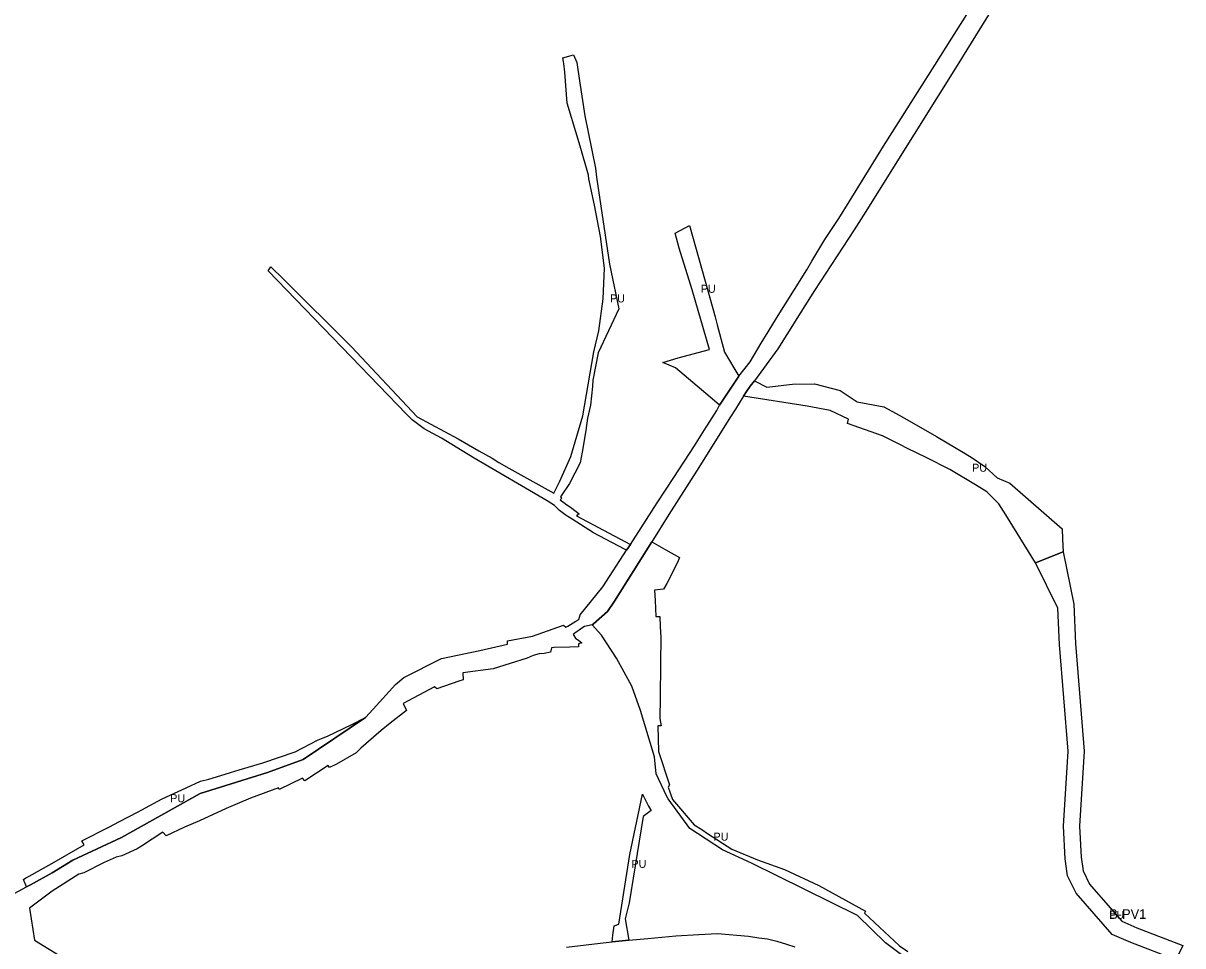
# Model space of a CAD drawing. Extents: x -532083 to -529750, y -1178838 to -1176858.
# Drawn here: x -530875 to -530150, y -1178327 to -1177750 of the extents above; entities that cross this region are included whole.
import ezdxf

# ---------------------------------------------------------------- set-up
doc = ezdxf.new("R2010")
doc.units = 0
for name, color, linetype in [('90320013', 7, 'Continuous'), ('90450013', 7, 'Continuous'), ('90450023', 7, 'Continuous'), ('ID_navrh', 7, 'Continuous')]:
    doc.layers.add(name, color=color, linetype=linetype)

msp = doc.modelspace()

# ---------------------------------------------------------------- linework, layer by layer
at = {"layer": '90320013'}
for points in [[(-530247.7753, -1177706.64445), (-530287.7503, -1177771.56645), (-530288.9793, -1177773.56145), (-530332.0333, -1177842.15945), (-530348.2853, -1177868.05345), (-530355.5573, -1177879.63945), (-530380.2003, -1177917.50445), (-530388.8553, -1177931.00945), (-530397.5103, -1177944.99745), (-530403.2813, -1177953.92045), (-530417.7243, -1177973.88745), (-530420.4543, -1177977.21245), (-530422.7943, -1177980.53745), (-530424.5493, -1177983.47145), (-530426.6943, -1177986.79645), (-530429.6423, -1177991.66345), (-530433.2363, -1177996.96545), (-530452.4703, -1178028.18145), (-530471.2763, -1178057.42145), (-530481.9363, -1178074.52945), (-530505.2853, -1178111.56745), (-530509.7313, -1178118.12545), (-530518.3933, -1178125.71245), (-530519.2923, -1178126.32345), (-530523.9963, -1178127.35645), (-530525.6703, -1178128.52545), (-530527.2973, -1178129.66245), (-530528.6113, -1178130.58045), (-530530.1423, -1178131.64945), (-530531.1543, -1178132.35645), (-530529.6733, -1178134.77045), (-530527.6183, -1178136.17545), (-530525.5993, -1178137.55645), (-530527.7423, -1178138.20145), (-530527.8573, -1178140.09545), (-530533.1463, -1178140.28645), (-530542.9003, -1178140.64045), (-530544.6823, -1178140.70545), (-530545.1933, -1178143.43745), (-530549.2893, -1178144.29845), (-530552.4043, -1178144.50445), (-530556.1973, -1178145.55845), (-530559.8083, -1178147.13345), (-530581.1013, -1178153.87845), (-530600.0073, -1178156.44745), (-530599.8853, -1178160.73045), (-530602.5523, -1178161.64245), (-530616.3523, -1178166.35845), (-530617.6943, -1178165.13445), (-530637.3323, -1178175.53445), (-530635.1853, -1178179.83545), (-530645.4633, -1178187.87945), (-530651.1763, -1178192.35145), (-530663.8973, -1178203.53145), (-530666.8043, -1178206.32645), (-530679.0403, -1178213.37445), (-530683.2823, -1178215.47645), (-530684.2773, -1178214.31245), (-530698.7003, -1178223.95745), (-530700.1923, -1178222.29445), (-530714.7803, -1178229.27845), (-530715.2773, -1178228.28045), (-530732.8503, -1178234.59945), (-530748.0513, -1178241.09045), (-530764.5753, -1178248.76345), (-530773.9073, -1178252.90745), (-530785.3823, -1178258.12545), (-530787.5243, -1178255.97645), (-530800.8353, -1178264.72445), (-530803.5423, -1178266.31545), (-530813.1453, -1178270.74545), (-530816.6623, -1178271.62945), (-530824.1723, -1178274.97445), (-530836.9833, -1178281.31845), (-530840.1153, -1178282.22545), (-530856.6683, -1178292.82245), (-530870.7843, -1178303.41145), (-530867.8193, -1178323.40045), (-530849.3143, -1178334.70345)], [(-530885.4993, -1178296.92945), (-530872.6603, -1178290.05245), (-530870.3363, -1178288.80845), (-530856.6793, -1178281.42345), (-530843.8433, -1178273.41945), (-530813.3143, -1178259.32645), (-530764.3073, -1178231.72545), (-530722.1703, -1178218.65745), (-530699.7783, -1178210.49045), (-530660.8983, -1178184.37845), (-530656.0243, -1178179.12745), (-530642.1243, -1178163.73545), (-530637.0023, -1178159.33245), (-530613.4693, -1178147.44045), (-530589.4053, -1178142.47145), (-530572.0653, -1178138.56645), (-530572.2423, -1178136.33645), (-530556.5383, -1178133.53645), (-530537.2423, -1178126.59945), (-530535.5983, -1178127.89845), (-530534.4113, -1178127.17845), (-530532.8013, -1178126.20345), (-530531.0833, -1178125.16245), (-530529.4133, -1178124.15045), (-530527.6153, -1178123.06045), (-530526.6923, -1178120.12245), (-530512.5303, -1178102.62545), (-530497.6963, -1178079.71545), (-530495.3163, -1178076.19345), (-530478.5523, -1178050.24945), (-530468.1603, -1178034.39445), (-530455.2993, -1178014.53245), (-530447.9233, -1178002.81745), (-530447.0513, -1178001.63445), (-530441.2613, -1177992.47645), (-530439.7033, -1177989.12545), (-530432.2213, -1177977.92045), (-530427.6603, -1177971.09045), (-530420.5063, -1177962.10045), (-530413.5103, -1177950.29845), (-530409.2173, -1177943.28145), (-530404.0333, -1177934.68845), (-530392.7173, -1177916.92145), (-530385.0903, -1177904.58345), (-530381.8923, -1177899.15445), (-530373.7743, -1177885.58245), (-530365.1643, -1177872.50345), (-530358.7143, -1177862.10845), (-530337.1083, -1177827.28945), (-530305.1713, -1177776.72145), (-530294.4153, -1177759.74045), (-530283.6203, -1177742.69945)], [(-530535.2303, -1178327.86345), (-530514.2903, -1178325.36245), (-530506.8323, -1178324.53145), (-530496.3413, -1178323.36245), (-530484.3753, -1178322.36245), (-530466.9243, -1178320.61145), (-530452.5173, -1178319.84045), (-530440.9613, -1178319.17245), (-530421.6263, -1178320.95545), (-530415.0533, -1178322.01545), (-530409.6093, -1178322.54345), (-530403.8143, -1178323.95245), (-530397.8443, -1178325.89045), (-530392.5753, -1178327.65245)]]:
    msp.add_lwpolyline(points, dxfattribs=at)
at = {"layer": '90450013'}
for points in [[(-530533.3373, -1178037.99045), (-530539.0373, -1178046.51045), (-530538.1823, -1178047.15445), (-530539.2083, -1178048.28945), (-530536.0123, -1178050.62945), (-530535.8623, -1178050.73945), (-530531.8453, -1178053.52845), (-530527.3933, -1178056.99245), (-530529.0033, -1178058.25645), (-530495.3163, -1178076.19345), (-530497.6963, -1178079.71545), (-530498.9473, -1178079.05445), (-530518.2923, -1178068.82645), (-530531.7033, -1178060.33845), (-530535.5073, -1178057.99445), (-530539.7053, -1178054.87845), (-530542.6973, -1178051.86345), (-530547.3553, -1178048.94245), (-530592.8793, -1178022.25645), (-530600.5643, -1178017.71045), (-530613.3743, -1178009.80245), (-530624.2133, -1178003.87245), (-530631.7043, -1177998.35545), (-530635.1583, -1177994.77845), (-530721.6223, -1177905.25045), (-530719.9673, -1177902.75145), (-530712.0353, -1177910.45945), (-530669.6483, -1177952.72845), (-530628.5003, -1177996.48945), (-530602.9683, -1178010.16445), (-530590.1143, -1178017.56745), (-530581.6473, -1178022.34545), (-530577.5483, -1178024.91945), (-530571.3823, -1178028.53745), (-530543.2263, -1178044.05945), (-530541.1323, -1178039.85745), (-530539.3873, -1178036.59045), (-530532.6323, -1178021.21245), (-530525.0113, -1177995.73245), (-530521.7003, -1177976.32445), (-530518.1973, -1177955.79045), (-530514.9573, -1177942.64045), (-530512.2773, -1177922.73045), (-530511.5373, -1177903.62045), (-530514.0573, -1177883.77045), (-530517.7673, -1177864.16045), (-530521.3773, -1177847.62045), (-530521.5673, -1177845.43045), (-530526.6873, -1177827.31045), (-530532.1673, -1177809.38045), (-530534.9073, -1177800.42045), (-530536.3273, -1177781.10045), (-530536.8473, -1177775.56045), (-530537.4563, -1177772.19345), (-530530.9773, -1177770.13845), (-530528.8123, -1177774.98245), (-530527.0693, -1177786.39845), (-530523.7273, -1177808.29445), (-530517.2123, -1177841.12945), (-530516.4183, -1177846.70745), (-530508.4383, -1177901.09845), (-530502.6283, -1177929.02645), (-530515.4893, -1177956.38545), (-530518.8153, -1177973.51245), (-530519.0373, -1177977.51645), (-530520.3153, -1177989.19045), (-530522.1413, -1177997.17145), (-530523.1853, -1178005.02045), (-530525.5593, -1178018.51045), (-530526.7383, -1178025.09845)], [(-530432.2213, -1177977.92045), (-530439.7033, -1177989.12545), (-530442.8203, -1177986.44545), (-530467.0923, -1177965.89545), (-530474.9823, -1177962.40345), (-530465.5673, -1177959.61645), (-530445.8983, -1177954.38045), (-530456.7093, -1177916.98245), (-530464.8373, -1177890.96345), (-530467.2963, -1177881.67845), (-530458.3293, -1177876.89045), (-530450.5283, -1177905.07245), (-530442.4413, -1177933.88545), (-530441.0473, -1177938.92045), (-530436.5843, -1177955.98445), (-530427.6603, -1177971.09045)], [(-530417.7243, -1177973.88745), (-530410.1203, -1177977.79845), (-530394.1303, -1177976.03845), (-530380.2853, -1177975.84345), (-530364.2963, -1177979.95045), (-530353.5713, -1177986.99145), (-530336.9963, -1177990.12145), (-530326.8563, -1177995.59845), (-530304.0423, -1178008.70245), (-530286.1023, -1178019.26545), (-530281.8123, -1178022.00345), (-530273.8173, -1178027.48045), (-530266.2133, -1178034.52145), (-530258.2183, -1178037.84645), (-530225.5703, -1178066.36445), (-530225.2533, -1178072.81645), (-530224.8663, -1178080.68945), (-530242.0943, -1178087.56745), (-530260.7533, -1178057.60145), (-530265.0433, -1178050.75545), (-530272.6473, -1178043.32345), (-530279.6673, -1178038.82445), (-530295.6573, -1178029.24045), (-530310.4773, -1178021.80745), (-530322.1763, -1178016.13545), (-530327.0513, -1178013.78845), (-530337.7763, -1178008.31145), (-530359.6163, -1178000.68345), (-530359.0313, -1177997.94545), (-530370.5353, -1177992.46845), (-530384.7703, -1177989.73045), (-530424.5493, -1177983.47145), (-530422.7943, -1177980.53745), (-530420.4543, -1177977.21245)], [(-530870.3363, -1178288.80845), (-530872.6603, -1178290.05245), (-530874.7093, -1178285.46045), (-530873.0813, -1178284.55645), (-530871.1003, -1178283.45545), (-530856.8843, -1178275.55945), (-530836.6683, -1178263.93345), (-530838.1693, -1178261.32345), (-530820.7903, -1178252.53245), (-530815.0483, -1178249.54345), (-530802.8733, -1178243.20645), (-530800.5643, -1178241.96345), (-530790.6673, -1178236.63745), (-530787.8553, -1178235.15145), (-530773.0483, -1178228.26845), (-530763.9793, -1178224.12445), (-530758.8313, -1178222.86345), (-530756.7633, -1178222.21845), (-530745.2753, -1178218.63745), (-530739.9203, -1178217.02845), (-530725.1193, -1178212.58245), (-530704.7593, -1178205.72445), (-530690.4333, -1178198.20245), (-530684.6663, -1178195.99845), (-530669.4363, -1178188.76445), (-530660.8983, -1178184.37845), (-530699.7783, -1178210.49045), (-530722.1703, -1178218.65745), (-530764.3073, -1178231.72545), (-530813.3143, -1178259.32645), (-530843.8433, -1178273.41945), (-530856.6793, -1178281.42345)], [(-530496.3413, -1178323.36245), (-530506.8323, -1178324.53145), (-530506.3123, -1178320.36145), (-530505.5643, -1178314.36045), (-530502.5733, -1178313.36045), (-530495.5933, -1178269.84945), (-530487.8263, -1178232.28045), (-530483.9383, -1178239.70945), (-530482.8273, -1178241.75245), (-530482.4573, -1178242.49545), (-530487.3313, -1178246.04845), (-530496.0913, -1178300.10645), (-530498.5843, -1178310.10945)]]:
    msp.add_lwpolyline(points, close=True, dxfattribs=at)
msp.add_lwpolyline([(-530320.8863, -1178336.36645), (-530335.9193, -1178325.05245), (-530353.4033, -1178307.91445), (-530419.7383, -1178275.30445), (-530437.7073, -1178267.06945), (-530458.1533, -1178253.70745), (-530471.7843, -1178235.06245), (-530472.6313, -1178233.59245), (-530479.2403, -1178219.53145), (-530480.2413, -1178208.88445), (-530489.0533, -1178179.95845), (-530494.4603, -1178164.69145), (-530504.0723, -1178147.21545), (-530513.4853, -1178132.75145), (-530519.2923, -1178126.32345), (-530518.3933, -1178125.71245), (-530509.7313, -1178118.12545), (-530505.2853, -1178111.56745), (-530481.9363, -1178074.52945), (-530473.1953, -1178079.44845), (-530464.6673, -1178084.36645), (-530465.9993, -1178087.34345), (-530472.5533, -1178100.49045), (-530474.6533, -1178104.17445), (-530480.2483, -1178104.64145), (-530479.7563, -1178111.25945), (-530479.5183, -1178121.22745), (-530476.9063, -1178121.16545), (-530476.7533, -1178127.57745), (-530476.3413, -1178134.01445), (-530476.5293, -1178150.45345), (-530476.7733, -1178171.79145), (-530476.9243, -1178184.96445), (-530476.0883, -1178189.46745), (-530478.2723, -1178189.46745), (-530477.8753, -1178205.60445), (-530470.8383, -1178226.29445), (-530471.6763, -1178227.80845), (-530468.9943, -1178235.54245), (-530455.4163, -1178251.34745), (-530450.7233, -1178254.20645), (-530447.2033, -1178256.72845), (-530431.9213, -1178266.47745), (-530415.9353, -1178273.23945), (-530398.9863, -1178279.22845), (-530377.6083, -1178289.27445), (-530348.3553, -1178305.24545), (-530348.9503, -1178306.50345), (-530327.1373, -1178326.88445), (-530321.9083, -1178330.48145)], dxfattribs=at)
at = {"layer": '90450023'}
msp.add_lwpolyline([(-530214.6993, -1178252.18345), (-530213.7103, -1178271.52945), (-530212.4393, -1178280.16945), (-530208.3353, -1178288.40145), (-530188.2193, -1178311.53945), (-530178.8193, -1178315.64945), (-530150.1113, -1178326.73345), (-530154.4243, -1178335.78745), (-530182.6253, -1178324.89945), (-530194.2883, -1178319.80045), (-530216.7173, -1178294.00245), (-530222.1003, -1178283.20345), (-530223.6733, -1178272.51545), (-530224.7153, -1178252.13345), (-530221.8493, -1178205.35845), (-530227.1863, -1178138.60145), (-530228.1323, -1178116.05145), (-530242.0943, -1178087.56745), (-530224.8663, -1178080.68945), (-530218.2293, -1178113.53445), (-530217.2033, -1178137.99345), (-530211.8243, -1178205.26545)], close=True, dxfattribs=at)

# ---------------------------------------------------------------- texts
at = {"layer": '90450013'}
for rotation, p in [(0.00000004, (-530508.02705, -1177924.92695)), (359.99999999, (-530451.3213, -1177918.91428)), (0.00000003, (-530281.74352, -1178030.72745)), (359.99999996, (-530782.89822, -1178237.21545)), (359.99999998, (-530443.3716, -1178261.24495)), (359.99999995, (-530494.6448, -1178278.22082))]:
    msp.add_text('PU', height=5, rotation=rotation, dxfattribs=at).set_placement(p)
at = {"layer": '90450023'}
msp.add_text('PU', height=5, rotation=359.99999998, dxfattribs=at).set_placement((-530196.1028, -1178310.09251))
at = {"layer": 'ID_navrh'}
msp.add_text('B-PV1', height=6, rotation=359.99999998, dxfattribs=at).set_placement((-530196.1028, -1178310.09251))

doc.saveas('drawing.dxf')
